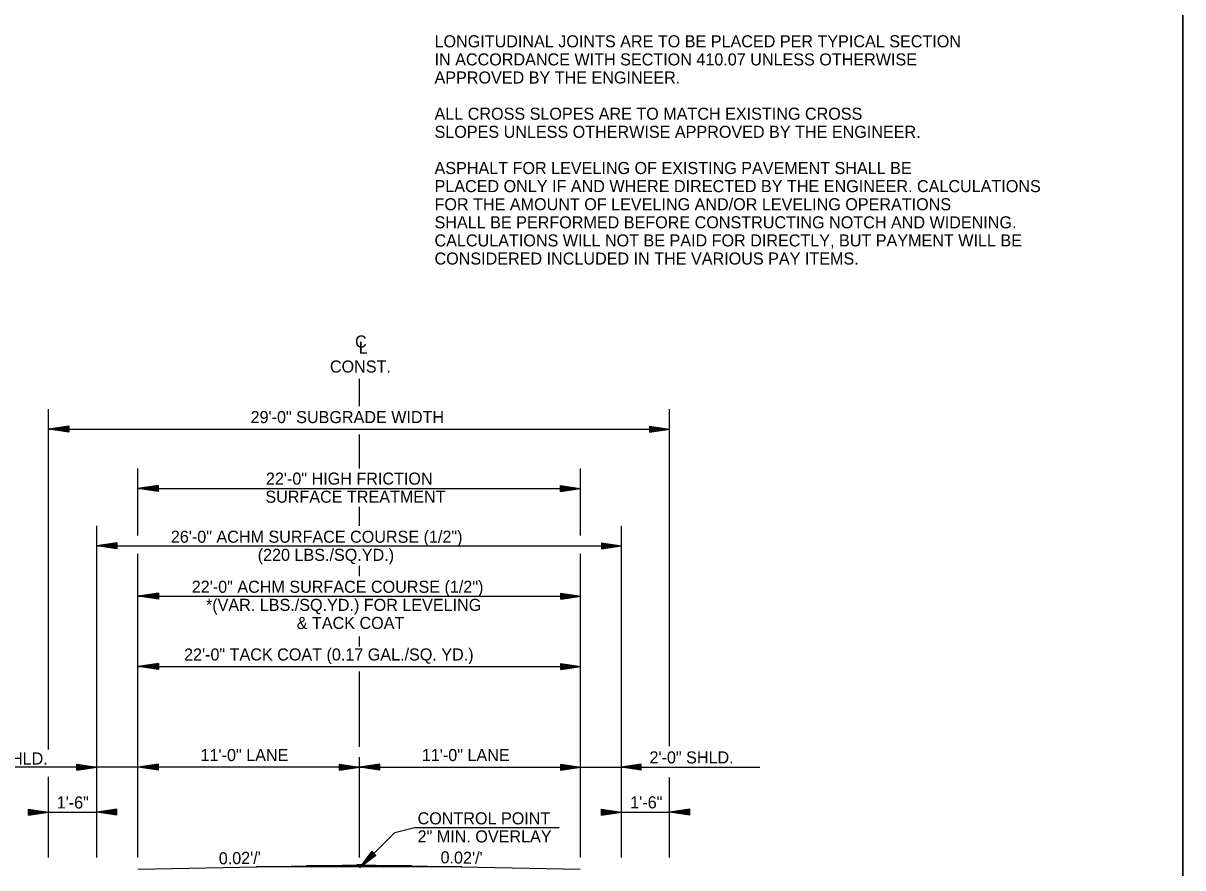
# Model space of a CAD drawing. Extents: x 2263886 to 2266026, y -3122850 to -3121850.
# Drawn here: x 2265299 to 2265356.6, y -3122421.1 to -3122379.1 of the extents above; entities that cross this region are included whole.
import ezdxf

# ---------------------------------------------------------------- set-up
doc = ezdxf.new("R2010")
doc.units = 0
for name, color, linetype in [('_CIVIL_CONSTRUCTION', 7, 'Continuous'), ('R_Border Notes', 7, 'Continuous'), ('R_Border Prem', 7, 'Continuous'), ('R_Draft', 7, 'Continuous')]:
    doc.layers.add(name, color=color, linetype=linetype)

msp = doc.modelspace()

# ---------------------------------------------------------------- linework, layer by layer
at = {"layer": '_CIVIL_CONSTRUCTION'}
msp.add_lwpolyline([(2265315.516, -3122339.098), (2265315.516, -3122344.038), (2265333.382, -3122344.038), (2265333.382, -3122345.498), (2265344.981, -3122345.498), (2265344.981, -3122357.664), (2265356.646, -3122357.664), (2265356.646, -3122441.828), (2265198.556, -3122441.828), (2265198.556, -3122339.098)], close=True, dxfattribs=at)
at = {"layer": 'R_Border Notes'}
for p, q in [((2265304.699, -3122421.206), (2265315.697, -3122420.986)), ((2265315.749, -3122421.088), (2265310.582, -3122421.088)), ((2265315.785, -3122421.038), (2265313.082, -3122421.038)), ((2265315.812, -3122420.988), (2265315.581, -3122420.988)), ((2265315.697, -3122420.986), (2265326.695, -3122421.206)), ((2265320.811, -3122421.088), (2265315.77, -3122421.088)), ((2265318.312, -3122421.038), (2265315.838, -3122421.038))]:
    msp.add_line(p, q, dxfattribs=at)
at = {"layer": 'R_Border Prem'}
for p, q in [((2265315.722, -3122398.171), (2265315.722, -3122396.821)), ((2265300.265, -3122415.245), (2265300.265, -3122398.321)), ((2265331.135, -3122415.09), (2265331.135, -3122398.321)), ((2265301.265, -3122399.171), (2265300.265, -3122399.321)), ((2265300.265, -3122399.321), (2265331.135, -3122399.321)), ((2265301.265, -3122399.471), (2265300.265, -3122399.321)), ((2265301.265, -3122399.196), (2265300.432, -3122399.321)), ((2265301.265, -3122399.446), (2265300.432, -3122399.321)), ((2265301.265, -3122399.221), (2265300.604, -3122399.321)), ((2265301.265, -3122399.42), (2265300.604, -3122399.321)), ((2265301.265, -3122399.246), (2265300.77, -3122399.321)), ((2265301.265, -3122399.395), (2265300.77, -3122399.321)), ((2265301.265, -3122399.272), (2265300.94, -3122399.321)), ((2265301.265, -3122399.37), (2265300.94, -3122399.321)), ((2265301.265, -3122399.297), (2265301.107, -3122399.321)), ((2265301.265, -3122399.344), (2265301.107, -3122399.321)), ((2265301.265, -3122399.171), (2265301.265, -3122399.471)), ((2265330.135, -3122399.171), (2265331.135, -3122399.321)), ((2265330.135, -3122399.171), (2265330.135, -3122399.471)), ((2265330.135, -3122399.196), (2265330.968, -3122399.321)), ((2265330.135, -3122399.221), (2265330.796, -3122399.321)), ((2265330.135, -3122399.246), (2265330.63, -3122399.321)), ((2265330.135, -3122399.272), (2265330.46, -3122399.321)), ((2265330.135, -3122399.297), (2265330.293, -3122399.321)), ((2265330.135, -3122399.471), (2265331.135, -3122399.321)), ((2265330.135, -3122399.37), (2265330.46, -3122399.321)), ((2265330.135, -3122399.42), (2265330.796, -3122399.321)), ((2265330.135, -3122399.446), (2265330.968, -3122399.321)), ((2265330.135, -3122399.395), (2265330.63, -3122399.321)), ((2265330.135, -3122399.344), (2265330.293, -3122399.321)), ((2265315.722, -3122401.275), (2265315.722, -3122399.596)), ((2265304.702, -3122404.611), (2265304.702, -3122401.275)), ((2265326.698, -3122404.611), (2265326.698, -3122401.275)), ((2265305.702, -3122402.125), (2265304.702, -3122402.275)), ((2265304.702, -3122402.275), (2265326.698, -3122402.275)), ((2265305.702, -3122402.425), (2265304.702, -3122402.275)), ((2265305.702, -3122402.15), (2265304.869, -3122402.275)), ((2265305.702, -3122402.4), (2265304.869, -3122402.275)), ((2265305.702, -3122402.175), (2265305.041, -3122402.275)), ((2265305.702, -3122402.374), (2265305.041, -3122402.275)), ((2265305.702, -3122402.2), (2265305.208, -3122402.275)), ((2265305.702, -3122402.349), (2265305.208, -3122402.275)), ((2265305.702, -3122402.226), (2265305.377, -3122402.275)), ((2265305.702, -3122402.324), (2265305.377, -3122402.275)), ((2265305.702, -3122402.251), (2265305.544, -3122402.275)), ((2265305.702, -3122402.298), (2265305.544, -3122402.275)), ((2265305.702, -3122402.125), (2265305.702, -3122402.425)), ((2265325.698, -3122402.125), (2265326.698, -3122402.275)), ((2265325.698, -3122402.125), (2265325.698, -3122402.425)), ((2265325.698, -3122402.15), (2265326.531, -3122402.275)), ((2265325.698, -3122402.175), (2265326.359, -3122402.275)), ((2265325.698, -3122402.2), (2265326.192, -3122402.275)), ((2265325.698, -3122402.226), (2265326.023, -3122402.275)), ((2265325.698, -3122402.251), (2265325.856, -3122402.275)), ((2265325.698, -3122402.425), (2265326.698, -3122402.275)), ((2265325.698, -3122402.324), (2265326.023, -3122402.275)), ((2265325.698, -3122402.374), (2265326.359, -3122402.275)), ((2265325.698, -3122402.4), (2265326.531, -3122402.275)), ((2265325.698, -3122402.349), (2265326.192, -3122402.275)), ((2265325.698, -3122402.298), (2265325.856, -3122402.275)), ((2265315.722, -3122404.124), (2265315.722, -3122403.179)), ((2265302.66, -3122420.624), (2265302.66, -3122404.124)), ((2265328.741, -3122420.624), (2265328.741, -3122404.124)), ((2265303.66, -3122404.974), (2265302.66, -3122405.124)), ((2265302.66, -3122405.124), (2265328.741, -3122405.124)), ((2265303.66, -3122405.274), (2265302.66, -3122405.124)), ((2265303.66, -3122404.999), (2265302.827, -3122405.124)), ((2265303.66, -3122405.249), (2265302.827, -3122405.124)), ((2265303.66, -3122405.024), (2265302.999, -3122405.124)), ((2265303.66, -3122405.223), (2265302.999, -3122405.124)), ((2265303.66, -3122405.049), (2265303.165, -3122405.124)), ((2265303.66, -3122405.198), (2265303.165, -3122405.124)), ((2265303.66, -3122405.075), (2265303.335, -3122405.124)), ((2265303.66, -3122405.173), (2265303.335, -3122405.124)), ((2265303.66, -3122405.1), (2265303.502, -3122405.124)), ((2265303.66, -3122405.147), (2265303.502, -3122405.124)), ((2265303.66, -3122404.974), (2265303.66, -3122405.274)), ((2265327.741, -3122404.974), (2265328.741, -3122405.124)), ((2265327.741, -3122404.974), (2265327.741, -3122405.274)), ((2265327.741, -3122404.999), (2265328.574, -3122405.124)), ((2265327.741, -3122405.024), (2265328.402, -3122405.124)), ((2265327.741, -3122405.049), (2265328.235, -3122405.124)), ((2265327.741, -3122405.075), (2265328.066, -3122405.124)), ((2265327.741, -3122405.1), (2265327.899, -3122405.124)), ((2265327.741, -3122405.274), (2265328.741, -3122405.124)), ((2265327.741, -3122405.173), (2265328.066, -3122405.124)), ((2265327.741, -3122405.223), (2265328.402, -3122405.124)), ((2265327.741, -3122405.249), (2265328.574, -3122405.124)), ((2265327.741, -3122405.198), (2265328.235, -3122405.124)), ((2265327.741, -3122405.147), (2265327.899, -3122405.124)), ((2265304.702, -3122420.624), (2265304.702, -3122405.522)), ((2265326.698, -3122420.624), (2265326.698, -3122405.522)), ((2265315.722, -3122406.624), (2265315.722, -3122406.124)), ((2265304.702, -3122407.624), (2265326.722, -3122407.624)), ((2265305.722, -3122407.474), (2265304.722, -3122407.624)), ((2265305.722, -3122407.774), (2265304.722, -3122407.624)), ((2265305.722, -3122407.499), (2265304.889, -3122407.624)), ((2265305.722, -3122407.749), (2265304.889, -3122407.624)), ((2265305.722, -3122407.524), (2265305.061, -3122407.624)), ((2265305.722, -3122407.723), (2265305.061, -3122407.624)), ((2265305.722, -3122407.549), (2265305.228, -3122407.624)), ((2265305.722, -3122407.698), (2265305.228, -3122407.624)), ((2265305.722, -3122407.575), (2265305.397, -3122407.624)), ((2265305.722, -3122407.673), (2265305.397, -3122407.624)), ((2265305.722, -3122407.6), (2265305.564, -3122407.624)), ((2265305.722, -3122407.647), (2265305.564, -3122407.624)), ((2265305.722, -3122407.474), (2265305.722, -3122407.774)), ((2265325.722, -3122407.474), (2265326.722, -3122407.624)), ((2265325.722, -3122407.774), (2265325.722, -3122407.474)), ((2265325.722, -3122407.499), (2265326.555, -3122407.624)), ((2265325.722, -3122407.524), (2265326.383, -3122407.624)), ((2265325.722, -3122407.549), (2265326.217, -3122407.624)), ((2265325.722, -3122407.575), (2265326.047, -3122407.624)), ((2265325.722, -3122407.6), (2265325.88, -3122407.624)), ((2265325.722, -3122407.774), (2265326.722, -3122407.624)), ((2265325.722, -3122407.672), (2265326.047, -3122407.624)), ((2265325.722, -3122407.723), (2265326.383, -3122407.624)), ((2265325.722, -3122407.749), (2265326.555, -3122407.624)), ((2265325.722, -3122407.698), (2265326.217, -3122407.624)), ((2265325.722, -3122407.647), (2265325.88, -3122407.624)), ((2265315.719, -3122410.124), (2265315.719, -3122409.624)), ((2265305.722, -3122410.974), (2265304.722, -3122411.124)), ((2265305.722, -3122410.999), (2265304.889, -3122411.124)), ((2265305.722, -3122411.024), (2265305.061, -3122411.124)), ((2265305.722, -3122411.049), (2265305.228, -3122411.124)), ((2265305.722, -3122411.075), (2265305.397, -3122411.124)), ((2265305.722, -3122410.974), (2265305.722, -3122411.274)), ((2265325.722, -3122410.974), (2265326.722, -3122411.124)), ((2265325.722, -3122411.274), (2265325.722, -3122410.974)), ((2265325.722, -3122410.999), (2265326.555, -3122411.124)), ((2265325.722, -3122411.024), (2265326.383, -3122411.124)), ((2265325.722, -3122411.049), (2265326.217, -3122411.124)), ((2265325.722, -3122411.075), (2265326.047, -3122411.124)), ((2265304.722, -3122411.124), (2265326.722, -3122411.124)), ((2265305.722, -3122411.274), (2265304.722, -3122411.124)), ((2265305.722, -3122411.249), (2265304.889, -3122411.124)), ((2265305.722, -3122411.223), (2265305.061, -3122411.124)), ((2265305.722, -3122411.198), (2265305.228, -3122411.124)), ((2265305.722, -3122411.173), (2265305.397, -3122411.124)), ((2265305.722, -3122411.1), (2265305.564, -3122411.124)), ((2265305.722, -3122411.147), (2265305.564, -3122411.124)), ((2265315.722, -3122415.124), (2265315.722, -3122411.374)), ((2265325.722, -3122411.1), (2265325.88, -3122411.124)), ((2265325.722, -3122411.274), (2265326.722, -3122411.124)), ((2265325.722, -3122411.172), (2265326.047, -3122411.124)), ((2265325.722, -3122411.223), (2265326.383, -3122411.124)), ((2265325.722, -3122411.249), (2265326.555, -3122411.124)), ((2265325.722, -3122411.198), (2265326.217, -3122411.124)), ((2265325.722, -3122411.147), (2265325.88, -3122411.124)), ((2265315.722, -3122420.624), (2265315.722, -3122415.624)), ((2265304.722, -3122416.124), (2265295.838, -3122416.124)), ((2265301.66, -3122415.974), (2265302.66, -3122416.124)), ((2265301.66, -3122416.274), (2265301.66, -3122415.974)), ((2265301.66, -3122415.999), (2265302.493, -3122416.124)), ((2265301.66, -3122416.024), (2265302.321, -3122416.124)), ((2265301.66, -3122416.049), (2265302.154, -3122416.124)), ((2265301.66, -3122416.075), (2265301.985, -3122416.124)), ((2265301.66, -3122416.1), (2265301.818, -3122416.124)), ((2265301.66, -3122416.274), (2265302.66, -3122416.124)), ((2265301.66, -3122416.172), (2265301.985, -3122416.124)), ((2265301.66, -3122416.223), (2265302.321, -3122416.124)), ((2265301.66, -3122416.249), (2265302.493, -3122416.124)), ((2265301.66, -3122416.198), (2265302.154, -3122416.124)), ((2265301.66, -3122416.147), (2265301.818, -3122416.124)), ((2265305.722, -3122415.974), (2265304.722, -3122416.124)), ((2265315.722, -3122416.124), (2265304.722, -3122416.124)), ((2265305.722, -3122416.274), (2265304.722, -3122416.124)), ((2265305.722, -3122415.999), (2265304.889, -3122416.124)), ((2265305.722, -3122416.249), (2265304.889, -3122416.124)), ((2265305.722, -3122416.024), (2265305.061, -3122416.124)), ((2265305.722, -3122416.223), (2265305.061, -3122416.124)), ((2265305.722, -3122416.049), (2265305.228, -3122416.124)), ((2265305.722, -3122416.198), (2265305.228, -3122416.124)), ((2265305.722, -3122416.075), (2265305.397, -3122416.124)), ((2265305.722, -3122416.172), (2265305.397, -3122416.124)), ((2265305.722, -3122416.1), (2265305.564, -3122416.124)), ((2265305.722, -3122416.147), (2265305.564, -3122416.124)), ((2265305.722, -3122416.274), (2265305.722, -3122415.974)), ((2265314.722, -3122415.974), (2265315.722, -3122416.124)), ((2265314.722, -3122416.274), (2265314.722, -3122415.974)), ((2265314.722, -3122415.999), (2265315.555, -3122416.124)), ((2265314.722, -3122416.024), (2265315.383, -3122416.124)), ((2265314.722, -3122416.049), (2265315.217, -3122416.124)), ((2265314.722, -3122416.075), (2265315.047, -3122416.124)), ((2265314.722, -3122416.1), (2265314.88, -3122416.124)), ((2265314.722, -3122416.274), (2265315.722, -3122416.124)), ((2265314.722, -3122416.172), (2265315.047, -3122416.124)), ((2265314.722, -3122416.223), (2265315.383, -3122416.124)), ((2265314.722, -3122416.249), (2265315.555, -3122416.124)), ((2265314.722, -3122416.198), (2265315.217, -3122416.124)), ((2265314.722, -3122416.147), (2265314.88, -3122416.124)), ((2265316.722, -3122415.974), (2265315.722, -3122416.124)), ((2265315.722, -3122416.124), (2265326.722, -3122416.124)), ((2265316.722, -3122416.274), (2265315.722, -3122416.124)), ((2265316.722, -3122415.999), (2265315.889, -3122416.124)), ((2265316.722, -3122416.249), (2265315.889, -3122416.124)), ((2265316.722, -3122416.024), (2265316.061, -3122416.124)), ((2265316.722, -3122416.223), (2265316.061, -3122416.124)), ((2265316.722, -3122416.049), (2265316.228, -3122416.124)), ((2265316.722, -3122416.198), (2265316.228, -3122416.124)), ((2265316.722, -3122416.075), (2265316.397, -3122416.124)), ((2265316.722, -3122416.172), (2265316.397, -3122416.124)), ((2265316.722, -3122416.1), (2265316.564, -3122416.124)), ((2265316.722, -3122416.147), (2265316.564, -3122416.124)), ((2265316.722, -3122416.274), (2265316.722, -3122415.974)), ((2265325.722, -3122415.974), (2265326.722, -3122416.124)), ((2265325.722, -3122416.274), (2265325.722, -3122415.974)), ((2265325.722, -3122415.999), (2265326.555, -3122416.124)), ((2265325.722, -3122416.024), (2265326.383, -3122416.124)), ((2265325.722, -3122416.049), (2265326.217, -3122416.124)), ((2265325.722, -3122416.075), (2265326.047, -3122416.124)), ((2265325.722, -3122416.1), (2265325.88, -3122416.124)), ((2265325.722, -3122416.274), (2265326.722, -3122416.124)), ((2265325.722, -3122416.172), (2265326.047, -3122416.124)), ((2265325.722, -3122416.223), (2265326.383, -3122416.124)), ((2265325.722, -3122416.249), (2265326.555, -3122416.124)), ((2265325.722, -3122416.198), (2265326.217, -3122416.124)), ((2265325.722, -3122416.147), (2265325.88, -3122416.124)), ((2265326.722, -3122416.124), (2265335.627, -3122416.124)), ((2265329.722, -3122415.974), (2265328.722, -3122416.124)), ((2265329.722, -3122416.274), (2265328.722, -3122416.124)), ((2265329.722, -3122415.999), (2265328.889, -3122416.124)), ((2265329.722, -3122416.249), (2265328.889, -3122416.124)), ((2265329.722, -3122416.024), (2265329.061, -3122416.124)), ((2265329.722, -3122416.223), (2265329.061, -3122416.124)), ((2265329.722, -3122416.049), (2265329.228, -3122416.124)), ((2265329.722, -3122416.198), (2265329.228, -3122416.124)), ((2265329.722, -3122416.075), (2265329.397, -3122416.124)), ((2265329.722, -3122416.172), (2265329.397, -3122416.124)), ((2265329.722, -3122416.1), (2265329.564, -3122416.124)), ((2265329.722, -3122416.147), (2265329.564, -3122416.124)), ((2265329.722, -3122416.274), (2265329.722, -3122415.974)), ((2265300.265, -3122420.624), (2265300.265, -3122416.615)), ((2265331.135, -3122420.624), (2265331.135, -3122416.636)), ((2265299.265, -3122418.216), (2265300.265, -3122418.366)), ((2265299.265, -3122418.516), (2265299.265, -3122418.216)), ((2265299.265, -3122418.241), (2265300.098, -3122418.366)), ((2265299.265, -3122418.267), (2265299.926, -3122418.366)), ((2265299.265, -3122418.292), (2265299.759, -3122418.366)), ((2265299.265, -3122418.317), (2265299.59, -3122418.366)), ((2265299.265, -3122418.343), (2265299.423, -3122418.366)), ((2265299.265, -3122418.516), (2265300.265, -3122418.366)), ((2265299.265, -3122418.415), (2265299.59, -3122418.366)), ((2265299.265, -3122418.466), (2265299.926, -3122418.366)), ((2265299.265, -3122418.491), (2265300.098, -3122418.366)), ((2265299.265, -3122418.441), (2265299.759, -3122418.366)), ((2265299.265, -3122418.39), (2265299.423, -3122418.366)), ((2265300.265, -3122418.366), (2265302.66, -3122418.366)), ((2265303.66, -3122418.216), (2265302.66, -3122418.366)), ((2265303.66, -3122418.516), (2265302.66, -3122418.366)), ((2265303.66, -3122418.241), (2265302.827, -3122418.366)), ((2265303.66, -3122418.491), (2265302.827, -3122418.366)), ((2265303.66, -3122418.267), (2265302.999, -3122418.366)), ((2265303.66, -3122418.466), (2265302.999, -3122418.366)), ((2265303.66, -3122418.292), (2265303.165, -3122418.366)), ((2265303.66, -3122418.441), (2265303.165, -3122418.366)), ((2265303.66, -3122418.317), (2265303.335, -3122418.366)), ((2265303.66, -3122418.415), (2265303.335, -3122418.366)), ((2265303.66, -3122418.343), (2265303.502, -3122418.366)), ((2265303.66, -3122418.39), (2265303.502, -3122418.366)), ((2265303.66, -3122418.516), (2265303.66, -3122418.216)), ((2265327.741, -3122418.216), (2265328.741, -3122418.366)), ((2265327.741, -3122418.516), (2265327.741, -3122418.216)), ((2265327.741, -3122418.241), (2265328.574, -3122418.366)), ((2265327.741, -3122418.267), (2265328.402, -3122418.366)), ((2265327.741, -3122418.292), (2265328.235, -3122418.366)), ((2265327.741, -3122418.317), (2265328.066, -3122418.366)), ((2265327.741, -3122418.343), (2265327.899, -3122418.366)), ((2265327.741, -3122418.516), (2265328.741, -3122418.366)), ((2265327.741, -3122418.415), (2265328.066, -3122418.366)), ((2265327.741, -3122418.466), (2265328.402, -3122418.366)), ((2265327.741, -3122418.491), (2265328.574, -3122418.366)), ((2265327.741, -3122418.441), (2265328.235, -3122418.366)), ((2265327.741, -3122418.39), (2265327.899, -3122418.366)), ((2265328.741, -3122418.366), (2265331.135, -3122418.366)), ((2265332.135, -3122418.216), (2265331.135, -3122418.366)), ((2265332.135, -3122418.516), (2265331.135, -3122418.366)), ((2265332.135, -3122418.241), (2265331.302, -3122418.366)), ((2265332.135, -3122418.491), (2265331.302, -3122418.366)), ((2265332.135, -3122418.267), (2265331.474, -3122418.366)), ((2265332.135, -3122418.466), (2265331.474, -3122418.366)), ((2265332.135, -3122418.292), (2265331.641, -3122418.366)), ((2265332.135, -3122418.441), (2265331.641, -3122418.366)), ((2265332.135, -3122418.317), (2265331.81, -3122418.366)), ((2265332.135, -3122418.415), (2265331.81, -3122418.366)), ((2265332.135, -3122418.343), (2265331.977, -3122418.366)), ((2265332.135, -3122418.39), (2265331.977, -3122418.366)), ((2265332.135, -3122418.516), (2265332.135, -3122418.216)), ((2265317.472, -3122419.374), (2265318.472, -3122419.124)), ((2265318.472, -3122419.124), (2265325.649, -3122419.124)), ((2265315.722, -3122421.124), (2265317.472, -3122419.374)), ((2265316.323, -3122420.31), (2265315.722, -3122421.124)), ((2265316.536, -3122420.523), (2265316.323, -3122420.31)), ((2265316.536, -3122420.523), (2265315.722, -3122421.124)), ((2265316.341, -3122420.328), (2265315.841, -3122421.005)), ((2265316.518, -3122420.505), (2265315.841, -3122421.005)), ((2265316.359, -3122420.346), (2265315.962, -3122420.884)), ((2265316.5, -3122420.487), (2265315.962, -3122420.884)), ((2265316.377, -3122420.364), (2265316.08, -3122420.766)), ((2265316.482, -3122420.469), (2265316.08, -3122420.766)), ((2265316.395, -3122420.382), (2265316.2, -3122420.646)), ((2265316.464, -3122420.451), (2265316.2, -3122420.646)), ((2265316.413, -3122420.4), (2265316.318, -3122420.528)), ((2265316.446, -3122420.433), (2265316.318, -3122420.528))]:
    msp.add_line(p, q, dxfattribs=at)
at = {"layer": 'R_Draft'}
msp.add_line((2265356.646, -3122441.828), (2265356.646, -3122339.098), dxfattribs=at)

# ---------------------------------------------------------------- texts
at = {"layer": 'R_Border Prem'}
for s, p in [('LONGITUDINAL JOINTS ARE TO BE PLACED PER TYPICAL SECTION', (2265319.448, -3122380.339)), ('IN ACCORDANCE WITH SECTION 410.07 UNLESS OTHERWISE', (2265319.448, -3122381.239)), ('APPROVED BY THE ENGINEER.', (2265319.448, -3122382.139)), ('ALL CROSS SLOPES ARE TO MATCH EXISTING CROSS ', (2265319.448, -3122383.939)), ('SLOPES UNLESS OTHERWISE APPROVED BY THE ENGINEER.', (2265319.448, -3122384.839)), ('ASPHALT FOR LEVELING OF EXISTING PAVEMENT SHALL BE', (2265319.448, -3122386.639)), ('PLACED ONLY IF AND WHERE DIRECTED BY THE ENGINEER. CALCULATIONS', (2265319.448, -3122387.539)), ('FOR THE AMOUNT OF LEVELING AND/OR LEVELING OPERATIONS', (2265319.448, -3122388.439)), ('SHALL BE PERFORMED BEFORE CONSTRUCTING NOTCH AND WIDENING.', (2265319.448, -3122389.339)), ('CALCULATIONS WILL NOT BE PAID FOR DIRECTLY, BUT PAYMENT WILL BE ', (2265319.448, -3122390.239)), ('CONSIDERED INCLUDED IN THE VARIOUS PAY ITEMS.', (2265319.448, -3122391.139)), ('C', (2265315.498, -3122395.264)), ('L', (2265315.678, -3122395.57)), ('CONST.', (2265314.249, -3122396.508)), ('29\'-0" SUBGRADE WIDTH', (2265310.304, -3122399.021)), ('2\'-0" SHLD.', (2265296.038, -3122415.995)), ('11\'-0" LANE', (2265307.818, -3122415.824)), ('11\'-0" LANE', (2265318.818, -3122415.824)), ('2\'-0" SHLD.', (2265330.133, -3122415.942)), ('1\'-6"', (2265300.665, -3122418.182)), ('1\'-6"', (2265329.178, -3122418.175)), ('CONTROL POINT', (2265318.606, -3122418.971)), ('2" MIN. OVERLAY', (2265318.606, -3122419.871))]:
    msp.add_text(s, height=0.6, dxfattribs=at).set_placement(p)
for s, rotation, p in [('22\'-0" HIGH FRICTION ', 360, (2265311.067, -3122402.08)), ('SURFACE TREATMENT', 360, (2265311.039, -3122402.98)), ('26\'-0" ACHM SURFACE COURSE (1/2")', 360, (2265306.34, -3122404.97)), ('(220 LBS./SQ.YD.)', 360, (2265310.658, -3122405.87)), ('22\'-0" ACHM SURFACE COURSE (1/2")', 360, (2265307.379, -3122407.458)), ('*(VAR. LBS./SQ.YD.) FOR LEVELING', 360, (2265308.085, -3122408.358)), ('& TACK COAT', 360, (2265312.597, -3122409.258)), ('22\'-0" TACK COAT (0.17 GAL./SQ. YD.)', 360, (2265306.996, -3122410.824)), ("0.02'/'", 1.14576, (2265308.729, -3122420.963)), ("0.02'/'", 358.85424, (2265319.741, -3122420.904))]:
    msp.add_text(s, height=0.6, rotation=rotation, dxfattribs=at).set_placement(p)

doc.saveas('drawing.dxf')
